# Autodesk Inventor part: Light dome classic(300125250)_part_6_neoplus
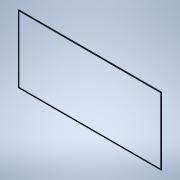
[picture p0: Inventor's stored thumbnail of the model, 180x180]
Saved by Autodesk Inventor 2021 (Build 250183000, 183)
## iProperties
Created: 2026-04
Part Number: Light dome classic(300125250)_part_6_neoplus
Material: Generic
Catalog Web Link: www.3dfindit.com
Description: Light dome classic_part_6_neoplus-
Vendor: KINGSPAN
Document SubType Name: Modeling
Designer: psAdmin
Manufacturer: KINGSPAN
Mass: 1345.27 g
Surface Area: 3724.49 cm^2
Volume: 1345.27 cm^3
Density: 1 g/cm^3
Appearance: PSOLRGB-128-128-128
Category: PARTsolutions
Company: KINGSPAN
Title: Light dome classic(300125250)_part_6_neoplus
Author: Cadenas PARTsolutions
PSOL_IDENT_0: {$CADENAS_DATA/23d-libs/kingspan_kla/light_dome_classic_neoplus/parts/part_6.prj},268 {VTYP=3D},{NB=
PSOL_IDENT_1: Light dome classic(300125250)_part_6_neoplus},{LINA=Light dome classic(300125250)_part_6_neoplus},{N
PSOL_IDENT_2: N=Light dome classic_part_6_neoplus},{DATE=20.03.2025 09:30:52},{GEOMDATE=27.10.2022 10:10:00},{VERS
PSOL_IDENT_3: ION=},{LINEID=10},{WBVAR=LODLEVEL,L,W},{WBNUMERIC=W}  {NB=Light dome classic(300125250)_part_6_neopl
PSOL_IDENT_4: us},{LINA=Light dome classic(300125250)_part_6_neoplus},{KT=DUMMY},{IDNR=},{PN=Light dome classic},{
PSOL_IDENT_5: LODLEVEL=300},{L=125},{W=250},{WX=125,250,300},{LX=1250},{XWX=2500}
NB: Light dome classic(300125250)_part_6_neoplus
NN: Light dome classic_part_6_neoplus
NBSYN: $PN.($LODLEVEL.$L.$W.)_part_6_neoplus
LINA: Light dome classic(300125250)_part_6_neoplus
CATALOG: Light + Air
PN: Light dome classic
LODLEVEL: 300
L: 125
W: 250
SUPPLIER: KINGSPAN
ARTICLENO: Light dome classic(300125250)_part_6_neoplus
BOMINFO: Light dome classic(300125250)_part_6_neoplus
CREATOR: CADENAS GmbH
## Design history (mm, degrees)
sketch "Sketch_1"
  geometry: L1 (-1173.235, 17.946)-(-1183.911, 17.946); L2 (-1185.365, 1.946)-(-1176.535, 1.946); L3 (-1174.735, 12.349)-(-1173.235, 17.946); A1 r 12.5 centre (-1175.1, 9.079) between (-1183.911, 17.946) and (-1185.365, 1.946); A2 r 12.5 centre (-1186.8, 9.079) between (-1176.535, 1.946) and (-1174.735, 12.349)
  constraints: 6 end point, 4 point on circle, 2 centre point
extrude "Extrusion1" join sketch "Sketch_1" stored distance "d0" = 2500; taper "d1" = 0 deg
sketch "Sketch_2"
  geometry: L1 (548.235, 17.946)-(549.735, 12.349); L2 (551.535, 1.946)-(560.365, 1.946); L3 (558.911, 17.946)-(548.235, 17.946); A1 r 12.5 centre (561.8, 9.079) between (549.735, 12.349) and (551.535, 1.946); A2 r 12.5 centre (550.1, 9.079) between (560.365, 1.946) and (558.911, 17.946)
  constraints: 6 end point, 4 point on circle, 2 centre point
extrude "Extrusion2" join sketch "Sketch_2" stored distance "d2" = 5000; taper "d3" = 0 deg
sketch "Sketch_3"
  geometry: L1 (1183.911, 17.946)-(1173.235, 17.946); L2 (1173.235, 17.946)-(1174.735, 12.349); L3 (1176.535, 1.946)-(1185.365, 1.946); A1 r 12.5 centre (1175.1, 9.079) between (1185.365, 1.946) and (1183.911, 17.946); A2 r 12.5 centre (1186.8, 9.079) between (1174.735, 12.349) and (1176.535, 1.946)
  constraints: 6 end point, 4 point on circle, 2 centre point
extrude "Extrusion3" join sketch "Sketch_3" stored distance "d4" = 2500; taper "d5" = 0 deg
sketch "Sketch_4"
  geometry: L1 (-548.235, 17.946)-(-558.911, 17.946); L2 (-560.365, 1.946)-(-551.535, 1.946); L3 (-549.735, 12.349)-(-548.235, 17.946); A1 r 12.5 centre (-550.1, 9.079) between (-558.911, 17.946) and (-560.365, 1.946); A2 r 12.5 centre (-561.8, 9.079) between (-551.535, 1.946) and (-549.735, 12.349)
  constraints: 6 end point, 4 point on circle, 2 centre point
extrude "Extrusion4" join sketch "Sketch_4" stored distance "d6" = 5000; taper "d7" = 0 deg
sketch "Sketch_5"
  geometry: L1 (-1179.25, 37.946)-(-2500, 37.946); L2 (-2500, 37.946)-(-2500, -12.054); L3 (-2500, -12.054)-(-1186.988, -12.054); L4 (-1186.988, -12.054)-(-1186.988, 5.216); L5 (-1183.911, 17.946)-(-1179.25, 17.946); L6 (-1179.25, 17.946)-(-1179.25, 37.946); A1 r 12.5 centre (-1175.1, 9.079) between (-1183.911, 17.946) and (-1186.988, 5.216)
  constraints: 12 end point, 2 point on circle, 1 centre point
extrude "Extrusion5" cut sketch "Sketch_5" stored distance "d8" = 5000; taper "d9" = 0 deg
sketch "Sketch_6"
  geometry: L1 (2500, -12.054)-(2500, 37.946); L2 (2500, 37.946)-(1179.25, 37.946); L3 (1179.25, 37.946)-(1179.25, 17.946); L4 (1179.25, 17.946)-(1183.911, 17.946); L5 (1186.988, 5.216)-(1186.988, -12.054); L6 (1186.988, -12.054)-(2500, -12.054); A1 r 12.5 centre (1175.1, 9.079) between (1186.988, 5.216) and (1183.911, 17.946)
  constraints: 12 end point, 2 point on circle, 1 centre point
extrude "Extrusion6" cut sketch "Sketch_6" stored distance "d10" = 5000; taper "d11" = 0 deg
sketch "Sketch_7"
  geometry: L1 (554.25, 37.946)-(554.25, 17.946); L2 (554.25, 17.946)-(558.911, 17.946); L3 (561.988, 5.216)-(561.988, -12.054); L4 (561.988, -12.054)-(2500, -12.054); L5 (2500, -12.054)-(2500, 37.946); L6 (2500, 37.946)-(554.25, 37.946); A1 r 12.5 centre (550.1, 9.079) between (561.988, 5.216) and (558.911, 17.946)
  constraints: 12 end point, 2 point on circle, 1 centre point
extrude "Extrusion7" cut sketch "Sketch_7" stored distance "d12" = 5000; taper "d13" = 0 deg
sketch "Sketch_8"
  geometry: L1 (-554.25, 37.946)-(-2500, 37.946); L2 (-2500, 37.946)-(-2500, -12.054); L3 (-2500, -12.054)-(-561.988, -12.054); L4 (-561.988, -12.054)-(-561.988, 5.216); L5 (-558.911, 17.946)-(-554.25, 17.946); L6 (-554.25, 17.946)-(-554.25, 37.946); A1 r 12.5 centre (-550.1, 9.079) between (-558.911, 17.946) and (-561.988, 5.216)
  constraints: 12 end point, 2 point on circle, 1 centre point
extrude "Extrusion8" cut sketch "Sketch_8" stored distance "d14" = 5000; taper "d15" = 0 deg
sketch "Sketch_10"
  geometry: L1 (-1180.95, -7.054)-(-1180.95, -1.143); L2 (-1187.201, 5.946)-(-1193.235, 5.946); L3 (-1193.235, 5.946)-(-1193.235, -7.054); L4 (-1193.235, -7.054)-(-1180.95, -7.054); A1 r 3.851 centre (-1180.95, 2.708) between (-1183.505, -0.173) and (-1180.95, -1.143); A2 r 12.5 centre (-1175.1, 9.079) between (-1187.201, 5.946) and (-1183.505, -0.173)
  constraints: 8 end point, 4 point on circle, 2 centre point
extrude "Extrusion9" cut sketch "Sketch_10" stored distance "d16" = 1250; taper "d17" = 0 deg
sketch "Sketch_11"
  geometry: L1 (568.235, 5.946)-(562.201, 5.946); L2 (555.95, -1.143)-(555.95, -7.054); L3 (555.95, -7.054)-(568.235, -7.054); L4 (568.235, -7.054)-(568.235, 5.946); A1 r 12.5 centre (550.1, 9.079) between (558.505, -0.173) and (562.201, 5.946); A2 r 3.851 centre (555.95, 2.708) between (555.95, -1.143) and (558.505, -0.173)
  constraints: 8 end point, 4 point on circle, 2 centre point
extrude "Extrusion10" cut sketch "Sketch_11" stored distance "d18" = 2500; taper "d19" = 0 deg
sketch "Sketch_12"
  geometry: L1 (1193.235, 5.946)-(1187.201, 5.946); L2 (1180.95, -1.143)-(1180.95, -7.054); L3 (1180.95, -7.054)-(1193.235, -7.054); L4 (1193.235, -7.054)-(1193.235, 5.946); A1 r 12.5 centre (1175.1, 9.079) between (1183.505, -0.173) and (1187.201, 5.946); A2 r 3.851 centre (1180.95, 2.708) between (1180.95, -1.143) and (1183.505, -0.173)
  constraints: 8 end point, 4 point on circle, 2 centre point
extrude "Extrusion11" cut sketch "Sketch_12" stored distance "d20" = 1250; taper "d21" = 0 deg
sketch "Sketch_13"
  geometry: L1 (-568.235, 5.946)-(-568.235, -7.054); L2 (-568.235, -7.054)-(-555.95, -7.054); L3 (-555.95, -7.054)-(-555.95, -1.143); L4 (-562.201, 5.946)-(-568.235, 5.946); A1 r 3.851 centre (-555.95, 2.708) between (-558.505, -0.173) and (-555.95, -1.143); A2 r 12.5 centre (-550.1, 9.079) between (-562.201, 5.946) and (-558.505, -0.173)
  constraints: 8 end point, 4 point on circle, 2 centre point
extrude "Extrusion12" cut sketch "Sketch_13" stored distance "d22" = 2500; taper "d23" = 0 deg
node "IP_6_XY"
node "IP_6_YZ"
node "IP_6_ZX"
node "IP_6_X"
node "IP_6_Y"
node "IP_6_Z"
node "IP_6_Center"
body "Solid1"
other parameters: "d24" = 0
